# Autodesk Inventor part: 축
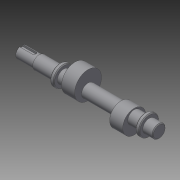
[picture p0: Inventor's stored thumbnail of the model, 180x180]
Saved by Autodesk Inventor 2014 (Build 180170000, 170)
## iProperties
Created: 2014-12
Part Number: 축
Material: 일반
Document SubType Name: Modeling
Designer: Owner
Density: 1 g/cm^3
Appearance: 기본값
Author: Owner
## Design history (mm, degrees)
sketch "스케치1"
  geometry: L1 (0, 0)-(180, 0); L2 (0, 0)-(0, 7.5); L3 (0, 7.5)-(24, 7.5); L4 (24, 7.5)-(24, 8.5); L5 (24, 8.5)-(51, 8.5); L6 (51, 8.5)-(51, 13); L7 (51, 13)-(56, 13); L8 (56, 13)-(56, 8.5); L9 (56, 8.5)-(162, 8.5); L10 (162, 8.5)-(162, 13); L11 (162, 13)-(167, 13); L12 (167, 13)-(167, 8.5); L13 (167, 8.5)-(180, 8.5); L14 (180, 8.5)-(180, 0); 1 further point
  constraints: 28 end point, 9 parallel, 4 perpendicular, 2 horizontal alignment, 1 coincident, 1 horizontal
  dimensions: "d0" = 180 distance of L1.start L1.end; "d1" = 24 distance of L2.end L3.end; "d2" = 27 distance of L4.end L5.end; "d3" = 5 distance of L6.end L7.end; "d4" = 15 diameter of L3 L1; "d5" = 17 diameter of L5 L1; "d6" = 26 diameter of L7 L1; "d7" = 13 distance of L12.end L13.end; "d8" = 5 distance of L10.end L11.end; "d9" = 26 diameter of L11 L1
revolve "회전1" sketch "스케치1" stored, may be unused: angle "d10" = 90 deg
node "작업 평면1"
sketch "스케치2"
  geometry: C1 r 17.5 at (0, 6); 1 further point
  constraints: 1 centre point, 1 vertical alignment
  dimensions: "d12" = 6 distance of point (0, 0) C1.centre; "d13" = 35 diameter of C1
extrude "돌출1" join sketch "스케치2" distance "d14" = 17; taper "d15" = 0 deg
node "작업 평면3"
sketch "스케치3"
  geometry: C1 r 15 at (0, -5); 1 further point
  constraints: 1 centre point, 1 vertical alignment
  dimensions: "d17" = 5 distance of C1.centre point (0, 0); "d18" = 30 diameter of C1
extrude "돌출2" join sketch "스케치3" distance "d19" = 17; taper "d20" = 0 deg
node "작업 평면6"
sketch "스케치4"
  geometry: L1 (10.5, 0)-(5.5, 0); L2 (-12, -2.5)-(5.5, -2.5); L3 (5.5, 2.5)-(-12, 2.5); L4 (-12, -7.5)-(-12, 7.5) reference; A1 r 2.5 centre (5.5, 0) between (5.5, -2.5) and (5.5, 2.5); 2 further points
  constraints: 8 end point, 3 point on circle, 2 parallel, 2 point on line, 2 tangent, 1 centre point, 1 horizontal, 1 horizontal alignment, 1 midpoint
  dimensions: "d21" = 5 distance between parallel lines of L2 L3; "d22" = 20 dimension on A1 L4
extrude "돌출3" cut sketch "스케치4" distance "d23" = 3; taper "d24" = 0 deg
chamfer "모따기1" distance "d25" = 1; stored, may be unused: second distance "d26" = 2, angle "d27" = 45 deg
chamfer "모따기2" distance "d28" = 1; stored, may be unused: second distance "d29" = 2, angle "d30" = 45 deg
chamfer "모따기3" distance "d31" = 1; stored, may be unused: second distance "d32" = 2, angle "d33" = 45 deg
node "솔리드1"
other parameters: "d11" = 70.5, "d16" = 147.5
